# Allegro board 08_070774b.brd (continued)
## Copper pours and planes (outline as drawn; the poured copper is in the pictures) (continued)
UNNAMED_5_CAP_I118_N1 on TOP: 62.6,62.2 62.6,56.2 67.5,56.2 67.5,62.2
UNNAMED_5_CN3P_I182_N1 on TOP: 21.4,63.6 21.4,67 22.2,67.8 22.2,71.8 19.4,71.8 19.4,63.6
UNNAMED_5_CN3P_I182_N3 on TOP: 11.39,63.6 11.39,67 12.19,67.8 12.19,71.8 9.39,71.8 9.39,63.6

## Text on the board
User.Comments: COMPONENTS GREATER THAN 1.5MM | COMPONENT KEEPOUT AREA | 2.    REPAIRS PER IPC-7711/21(LATEST REVISION) ARE ALLOWED. | 3.    REPAIRS ARE NOT ALLOWED IN SOLDERMASK FREE AREAS ON EITHER | SIDE OF THE BOARD. | 4.    RoHS COMPLIANCE: ASSEMBLY VENDOR SHOULD ASSURE COMPLIANCE | WITH LEAD-FREE AND RoHS PCB ASSEMBLY STANDARDS (EU RoHS | 5.    BOARDS TO BE SHIPPED SINGULATED AFTER ASSEMBLY PROCESS. | 6.    SMOOTHEN EDGES AND FREE FROM BURRS AFTER DEPANELIZATION PROCESS. | DIRECTIVE 2002/95/EC). | 7.    DO NOT TRIM/CUT EXCESS TAIL LENGTH FOR P1, P2, P3, AND P4. | 8.    INSTALL SHUNT CONNECTOR (M031256) TO THE FOLLOWING JUMPERS: | WIRE ENTRY | 8.    INSTALL SCREW (M025339) ON PRIMARY SIDE AND | LK1 - INSTALLED | LK2 - PIN 1 AND PIN 2 | LK3 - PIN 1 AND PIN 2 | LK4 - PIN 1 AND PIN 2 | STANDOFF (M057696) ON THE SECONDARY SIDE. | SEE NOTE #8 (6 PLACES)
Ref Des/Assembly Top: 1 | C | A
Ref Des/Silkscreen Top: 1 | 08-070774 REV B Z | EVAL-AD57X0ARDZ | PRIMARY SIDE | C | A
PAGE_OUTLINE: B | INITIAL RELEASE | 19JUN23 | J. PABALAN | CUSTOMER EVALUATION Z
DIMENSION: " " | (REF) | DIA MAX | - | SEE NOTE #17
User.10: L2 Internal GND | 08-      -07
User.11: L3 Internal GND | 08-      -08
User.13: ROHS COMPLIANCE | NOTE; | 17.    PANEL TO BE SUBJECTED TO CUSTOMER'S APPROVAL. | 15.    BOARDS TO BE SHIPPED IN ARRAYS AND KEEP INTACT. | 16.    PANELED SOLDER PASTE STENCIL SHOULD BE SENT TO THE CUSTOMER.
User.17: L2 GND | 08-      -06
User.18: L3 SIG | 08-      -07
User.19: L4 PWR | 08-      -08
User.20: L5 GND | 08-      -09
User.37: PER ECR-094468 | B | 28MAY20 | PD
User.39: TEMPLATE NOTES. | 01.COMPONENTS ARE PLACED ON THIS SIDE. | 02.CONNECTORS P1,P2.P4 & P5 ARE PLACED | ON THIS SIDE OF THE BOARD. | 03.IF THE BOARD NEEDS TO BE INCREASED | IT CAN BE INCREASED IN THE DIRECTION | OF THE ARROWS. | 04.THE BOARD IS SET-UP AS A 4 LAYER | BOARD. MAKE SURE ANY SUBSEQUENT CHANGES, | MANUAL OR AUTOMATIC, DO NOT RESULT IN | ANY UNINTENDED CONSEQUENCES. | 05.THE EXISTING ROUTING CAN BE ALTERED AS | IS ROUTED TO CLOSE THE NETS ON THE | TEMPLATE BOARD. | PAGE 1 OF 5 | TOP SIDE VIEW | VIEW OF SILKSCREEN, PINS, VIAS, | ETCH AND REFERENCE INFORMATION.
User.40: TEMPLATE NOTES. | 01.COMPONENTS ARE PLACED ON THIS SIDE. | 02.CONNECTORS P3 IS PLACED ON THIS SIDE. THE | OTHER CONNECTORS ARE SOLDERED THIS SIDE. | 03.THE TEMPLATE IS VIEWED LOOKING FROM THE | TOP SIDE OF THE BOARD. THE RESULT IS | THAT TEXT IS MIRRORED. | 04.THE BOARD IS SET-UP AS A 4 LAYER | BOARD. MAKE SURE ANY SUBSEQUENT CHANGES, | MANUAL OR AUTOMATIC, DO NOT RESULT IN | ANY UNINTENDED CONSEQUENCES. | PAGE 2 OF 5 | BOTTTOM SIDE VIEW | VIEW OF SILKSCREEN, PINS, VIAS, | ETCH AND REFERENCE INFORMATION.
User.41: PAGE 3 OF 5 | PCB FAB SHEET 1 | NCDRILL LEGEND, APPROPRIATE | DETAILS AND OUTLINE DIMENSION NOTES. | 01. EACH TIME THE NC DRILL LEGEND | IS RUN, THE HOLE CHART MUST BE | CHECKED TO ASSURE THE TOLERANCES | & NOTES CORRESPOND TO THE RIGHT | PADSTACKS.
User.42: PAGE 4 OF 5 | PCB FAB SHEET 2 | FABRICATION NOTES. ALTER DEPENDING ON THE | REQUIREMENTS OF THE DESIGN.
User.43: PROPERTIES FOR PCB DESIGN USE. | THEY MAINTAIN A SEPARATE TITLE BLOCK AND PART | NUMBER FOR REVISION TRACKING, INDEPENDENT OF | THE ACTUAL MANUFACTURED DUT-SPECIFIC BOARD | DESIGN. | TEMPLATE BOARDS DISPLAY AS "FILE VIEWS", AND | DUT-SPECIFIC APPLICATION BOARDS ARE | MANUFACTURED FROM ARTWORK "FILM VIEWS"AND NC | DATA. | AND TITLE BLOCK CONTENT IS TRACKING THE | MANUFACTURED BOARD PART NUMBER AND REV, | AND NOT THE TEMPLATE BOARD PART NUMBER AND | REV. | MAKE SURE THE DUT-SPECIFIC BOARD INFORMATION | REV.A (20APR20) | 1. INITIAL RELEASE. | TEMPLATE REVISION HISTORY | TEMPLATE BOARDS FOR EVAL PROVIDE INFORMATION IN THE | 5-VIEW "PDF FORMAT" FOR EVAL ENGINEERING | REFERENCE; ALONG WITH EMBEDDED ALLEGRO | PAGE 5 OF 5 | REV.B (28MAY20) PER ECR-094468 | 1. BRING FILES INTO TEMPLATE FORMAT.
User.45: 1 | FABRICATION | 09-012345-01 | A | FIGURE | SIZE | 0.254 | 0.762 | 1.016 | 1.143 | 1.1684 | 1.27 | 1.6002 | 1.7018 | 3.175 | DRILL CHART: TOP to BOTTOM | FINISHED HOLES IN MILLIMETERS | PLATED | NON-PLATED | QTY | 289 | 27 | 18 | 53 | 2 | 3 | 7 | 8 | 6 | TOLERANCE/NOTES
